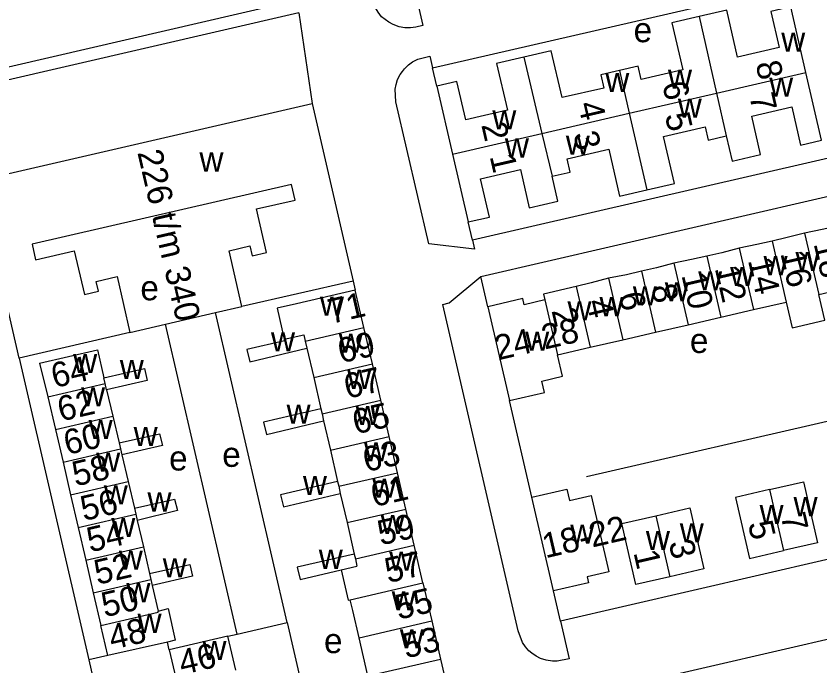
# Model space of a CAD drawing. Extents: x 155696 to 157795, y 382328 to 384028.
# Drawn here: x 156988.1 to 157117.5, y 383345.7 to 383450.5 of the extents above; entities that cross this region are included whole.
import ezdxf

# ---------------------------------------------------------------- set-up
doc = ezdxf.new("R2010")
doc.units = 0
for name, color, linetype in [('BLT_Basislijn', 7, 'Continuous'), ('BLT_Bebouwing', 7, 'Continuous'), ('BLT_Centroide', 7, 'Continuous'), ('BLT_Huisnummer', 7, 'Continuous'), ('BLT_Huisnummer_ tussenligend', 7, 'Continuous'), ('BLT_Huisnummer_reeks', 7, 'Continuous'), ('BLT_Onderverdeling_panden', 7, 'Continuous'), ('BLT_Vlakafsluiter', 7, 'Continuous')]:
    doc.layers.add(name, color=color, linetype=linetype)

msp = doc.modelspace()

# ---------------------------------------------------------------- linework, layer by layer
at = {"layer": 'BLT_Basislijn'}
for p, q in [((157055.84, 383439.14), (157055.17, 383442.1)), ((157061.59, 383414.33), (157060.9, 383417.29)), ((157042.38, 383407.74), (157042.71, 383406.28)), ((157020.2, 383402.66), (157024.45, 383403.65)), ((157012.15, 383400.78), (157020.2, 383402.66)), ((157031.74, 383352.71), (157020.2, 383402.66)), ((157006.4, 383399.44), (157012.15, 383400.78)), ((157023.69, 383350.85), (157012.15, 383400.78)), ((156988.59, 383395.32), (156999.79, 383346.69)), ((157079.95, 383376.24), (157134.89, 383388.93)), ((157023.69, 383350.85), (157031.74, 383352.71)), ((157031.74, 383352.71), (157043.15, 383303.31)), ((157022.19, 383350.5), (157023.69, 383350.85)), ((157012.74, 383348.32), (157012.45, 383349.58)), ((157002.84, 383347.39), (156999.79, 383346.69)), ((156999.79, 383346.69), (157000.9, 383341.9))]:
    msp.add_line(p, q, dxfattribs=at)
for points in [[(157052.14, 383455.26), (157053.59, 383448.93), (157052.46, 383448.65), (157051.62, 383448.56), (157050.71, 383448.57), (157049.79, 383448.74), (157048.82, 383449.07), (157048.11, 383449.45), (157046.95, 383450.35), (157046.39, 383451.07), (157045.95, 383451.78), (157045.59, 383452.7), (157045.31, 383453.68), (157039.57, 383478.52), (157040.6, 383478.76), (157045.72, 383483.02)], [(157055.17, 383442.1), (157119.26, 383456.9)], [(157119.26, 383456.9), (157125.67, 383429.13), (157061.59, 383414.33)], [(157033.62, 383450.98), (156911.34, 383422.73)], [(157061.59, 383414.33), (157061.92, 383412.88), (157054.54, 383413.74), (157049.25, 383436.64), (157049.13, 383438.66), (157049.3, 383439.42), (157049.52, 383440.21), (157049.94, 383441.03), (157050.31, 383441.54), (157050.62, 383441.97), (157051.28, 383442.61), (157051.93, 383443.08), (157052.79, 383443.52), (157054.74, 383443.98), (157055.17, 383442.1)], [(157062.94, 383408.49), (157127.02, 383423.29), (157135.23, 383387.74)], [(157075.77, 383352.95), (157077.17, 383346.85), (157075.2, 383346.51), (157074.45, 383346.49), (157073.46, 383346.64), (157072.54, 383346.93), (157071.86, 383347.28), (157071.14, 383347.8), (157070.68, 383348.17), (157070.12, 383348.8), (157069.65, 383349.49), (157068.94, 383351.38), (157056.79, 383403.99), (157057.81, 383404.23), (157062.94, 383408.49)], [(157064.06, 383403.61), (157062.94, 383408.49)], [(157071.15, 383372.94), (157067.56, 383388.49)], [(157139.85, 383367.75), (157075.77, 383352.95)], [(157075.77, 383352.95), (157074.64, 383357.82)], [(157078.58, 383340.77), (157142.66, 383355.57), (157152.05, 383314.94)]]:
    msp.add_lwpolyline(points, dxfattribs=at)
at = {"layer": 'BLT_Bebouwing'}
for p, q in [((157115.3, 383441.36), (157112.86, 383451.95)), ((157055.84, 383439.14), (157058.38, 383428.22)), ((157042.38, 383407.74), (157024.45, 383403.65)), ((157042.71, 383406.28), (157033.26, 383404.1)), ((157044.11, 383400.24), (157042.71, 383406.28)), ((157117.38, 383405.58), (157122.64, 383406.8)), ((157106.85, 383403.15), (157112.12, 383404.37)), ((157030.12, 383403.37), (157031.27, 383398.36)), ((157101.59, 383401.94), (157106.85, 383403.15)), ((157096.33, 383400.72), (157101.59, 383401.94)), ((157091.07, 383399.51), (157096.33, 383400.72)), ((157006.4, 383399.44), (156988.59, 383395.32)), ((157045.46, 383394.4), (157044.11, 383400.24)), ((157085.81, 383398.29), (157091.07, 383399.51)), ((157080.55, 383397.08), (157085.81, 383398.29)), ((156991.85, 383394.54), (157001.19, 383396.67)), ((157001.19, 383396.67), (157002.2, 383392.17)), ((157034.91, 383396.91), (157036.01, 383392.21)), ((157075.29, 383395.86), (157080.55, 383397.08)), ((156991.85, 383394.54), (156993.21, 383389.1)), ((157046.81, 383388.55), (157045.46, 383394.4)), ((157036.01, 383392.21), (157037.16, 383387.14)), ((157002.65, 383390.24), (157003.66, 383385.97)), ((156993.21, 383389.1), (156994.43, 383383.84)), ((157048.16, 383382.71), (157046.81, 383388.55)), ((157003.66, 383385.97), (157004.67, 383381.66)), ((157037.61, 383385.2), (157038.71, 383380.52)), ((156994.43, 383383.84), (156995.64, 383378.57)), ((157049.51, 383376.86), (157048.16, 383382.71)), ((157005.11, 383379.76), (157006.12, 383375.45)), ((157038.71, 383380.52), (157039.85, 383375.45)), ((156995.64, 383378.57), (156996.86, 383373.31)), ((157050.86, 383371.01), (157049.51, 383376.86)), ((157006.12, 383375.45), (157007.13, 383371.15)), ((156996.86, 383373.31), (156998.07, 383368.05)), ((157040.29, 383373.52), (157041.41, 383368.83)), ((157052.21, 383365.17), (157050.86, 383371.01)), ((157007.6, 383369.18), (157008.57, 383364.93)), ((157041.41, 383368.83), (157042.54, 383363.76)), ((156998.07, 383368.05), (156999.29, 383362.79)), ((157008.57, 383364.93), (157009.56, 383360.62)), ((157053.61, 383359.12), (157052.21, 383365.17)), ((156999.29, 383362.79), (157000.5, 383357.53)), ((157053.61, 383359.12), (157055.02, 383352.98)), ((157010.01, 383358.67), (157010.94, 383354.57)), ((157000.5, 383357.53), (157001.72, 383352.26)), ((157042.32, 383354.66), (157041.9, 383356.39)), ((157043.33, 383350.28), (157042.32, 383354.66)), ((157055.02, 383352.98), (157056.44, 383346.84)), ((157002.84, 383347.39), (157001.72, 383352.26)), ((157022.19, 383350.5), (157012.74, 383348.32)), ((157023.45, 383345.04), (157022.19, 383350.5)), ((157044.75, 383344.14), (157043.33, 383350.28)), ((157012.45, 383349.58), (157002.84, 383347.39)), ((157013.71, 383349.87), (157012.45, 383349.58)), ((157012.74, 383348.32), (157014, 383342.86)), ((157056.44, 383346.84), (157057.86, 383340.7))]:
    msp.add_line(p, q, dxfattribs=at)
msp.add_lwpolyline([(156963.49, 383462.53), (157024.61, 383476.65), (157030.25, 383452.25), (156920.89, 383426.99), (156941.26, 383444.13), (156972.68, 383451.38)], close=True, dxfattribs=at)
for points in [[(157112.86, 383451.95), (157109.63, 383451.2), (157110.97, 383445.38), (157104.28, 383443.83), (157102.54, 383451.39), (157098.12, 383450.37)], [(157098.12, 383450.37), (157093.71, 383449.35), (157095.46, 383441.79), (157088.75, 383440.24), (157088.25, 383442.39), (157085.25, 383441.69)], [(157085.25, 383441.69), (157082.24, 383441), (157082.74, 383438.86), (157076.03, 383437.31), (157074.28, 383444.87), (157069.87, 383443.85)], [(157069.87, 383443.85), (157065.45, 383442.83), (157067.2, 383435.27), (157060.49, 383433.72), (157059.08, 383439.89), (157055.84, 383439.14)], [(157102.47, 383431.13), (157103.4, 383427.09), (157107.98, 383428.15), (157106.56, 383434.33), (157113, 383435.82), (157114.42, 383429.66), (157117.82, 383430.44), (157115.3, 383441.36)], [(156988.59, 383395.32), (156981.98, 383423.96), (157035.76, 383436.39)], [(157035.76, 383436.39), (157042.38, 383407.74)], [(157089.69, 383422.47), (157094.1, 383423.49), (157092.35, 383431.05), (157099.06, 383432.6), (157099.56, 383430.46), (157102.47, 383431.13)], [(157074.4, 383424.65), (157077.31, 383425.32), (157076.82, 383427.46), (157083.53, 383429.01), (157085.27, 383421.45), (157089.69, 383422.47)], [(157058.38, 383428.22), (157060.9, 383417.29)], [(157060.9, 383417.29), (157064.31, 383418.07), (157062.88, 383424.24), (157069.31, 383425.73), (157070.74, 383419.54), (157075.34, 383420.6), (157074.4, 383424.65)], [(157024.45, 383403.65), (157022.38, 383412.64), (157025.73, 383413.41), (157026.1, 383411.81), (157028.39, 383412.34), (157026.77, 383419.37), (157033.02, 383420.81), (157032.45, 383423.32), (156990.64, 383413.67), (156991.2, 383411.19), (156997.45, 383412.62), (156999.07, 383405.58), (157001.34, 383406.1), (157000.98, 383407.69), (157004.33, 383408.46), (157006.4, 383399.44)], [(157120.37, 383416.62), (157117.93, 383416.06), (157115.08, 383415.49)], [(157115.08, 383415.49), (157112.28, 383414.75), (157109.85, 383414.19)], [(157109.85, 383414.19), (157107.41, 383413.63), (157104.55, 383413.06)], [(157104.55, 383413.06), (157101.76, 383412.32), (157099.32, 383411.76)], [(157099.32, 383411.76), (157096.89, 383411.2), (157094.03, 383410.63)], [(157094.03, 383410.63), (157091.24, 383409.89), (157088.8, 383409.33)], [(157088.8, 383409.33), (157086.37, 383408.77), (157083.5, 383408.19)], [(157083.5, 383408.19), (157080.71, 383407.46), (157078.28, 383406.9)], [(157078.28, 383406.9), (157073.02, 383405.64), (157073.24, 383404.71)], [(157073.24, 383404.71), (157069.92, 383403.94), (157069.69, 383404.92), (157064.06, 383403.61)], [(157112.12, 383404.37), (157113.06, 383400.23), (157118.33, 383401.44), (157117.38, 383405.58)], [(157033.26, 383404.1), (157030.12, 383403.37)], [(157064.06, 383403.61), (157067.56, 383388.49)], [(157031.27, 383398.36), (157031.33, 383398.12), (157025.25, 383396.7), (157025.7, 383394.76), (157034.91, 383396.91)], [(157067.56, 383388.49), (157073.19, 383389.79), (157072.76, 383391.64), (157076.08, 383392.41), (157075.29, 383395.86)], [(157002.2, 383392.17), (157008.73, 383393.65), (157009.19, 383391.73), (157002.65, 383390.24)], [(157037.16, 383387.14), (157027.95, 383385), (157028.41, 383383.05), (157037.61, 383385.2)], [(157004.67, 383381.66), (157011.17, 383383.14), (157011.63, 383381.24), (157005.11, 383379.76)], [(157039.85, 383375.45), (157030.66, 383373.31), (157031.12, 383371.38), (157040.29, 383373.52)], [(157109.43, 383374.15), (157114.9, 383375.41), (157117.17, 383365.59), (157111.7, 383364.33)], [(157071.15, 383372.94), (157076.78, 383374.24), (157077.21, 383372.39), (157080.71, 383373.2), (157080.71, 383373.2)], [(157109.43, 383374.15), (157103.97, 383372.89), (157106.23, 383363.06), (157111.7, 383364.33)], [(157007.13, 383371.15), (157013.6, 383372.62), (157014.05, 383370.76), (157007.6, 383369.18)], [(157074.64, 383357.82), (157071.15, 383372.94)], [(157080.71, 383373.2), (157083.55, 383360.91)], [(157091.12, 383369.92), (157096.58, 383371.18), (157098.85, 383361.36), (157093.39, 383360.1)], [(157093.39, 383360.1), (157087.92, 383358.83), (157085.65, 383368.66), (157091.12, 383369.92)], [(157042.54, 383363.76), (157033.36, 383361.62), (157033.81, 383359.68), (157040.46, 383361.22)], [(157009.56, 383360.62), (157016.06, 383362.1), (157016.49, 383360.17), (157010.01, 383358.67)], [(157040.46, 383361.22), (157041.56, 383356.32), (157041.9, 383356.39)], [(157083.55, 383360.91), (157080.05, 383360.09), (157080.27, 383359.12), (157074.64, 383357.82)], [(157010.94, 383354.57), (157012.55, 383354.96), (157013.71, 383349.87)]]:
    msp.add_lwpolyline(points, dxfattribs=at)
at = {"layer": 'BLT_Onderverdeling_panden'}
for p, q in [((157098.12, 383450.37), (157100.91, 383438.04)), ((157069.87, 383443.85), (157072.78, 383431.54)), ((157085.25, 383441.69), (157086.84, 383434.79)), ((157100.91, 383438.04), (157115.3, 383441.36)), ((157086.84, 383434.79), (157100.91, 383438.04)), ((157100.91, 383438.04), (157102.47, 383431.13)), ((157072.78, 383431.54), (157086.84, 383434.79)), ((157086.84, 383434.79), (157089.69, 383422.47)), ((157058.38, 383428.22), (157072.78, 383431.54)), ((157072.78, 383431.54), (157074.4, 383424.65)), ((157115.08, 383415.49), (157117.38, 383405.58)), ((157109.85, 383414.19), (157112.12, 383404.37)), ((157104.55, 383413.06), (157106.85, 383403.15)), ((157099.32, 383411.76), (157101.59, 383401.94)), ((157094.03, 383410.63), (157096.33, 383400.72)), ((157088.8, 383409.33), (157091.07, 383399.51)), ((157083.5, 383408.19), (157085.81, 383398.29)), ((157078.28, 383406.9), (157080.55, 383397.08)), ((157073.24, 383404.71), (157075.29, 383395.86)), ((157034.66, 383398.06), (157044.11, 383400.24)), ((157034.42, 383399.08), (157034.66, 383398.06)), ((157034.66, 383398.06), (157034.91, 383396.91)), ((157036.01, 383392.21), (157045.46, 383394.4)), ((157002.42, 383391.22), (157002.2, 383392.17)), ((156993.21, 383389.1), (157002.42, 383391.22)), ((157002.65, 383390.24), (157002.42, 383391.22)), ((157037.36, 383386.37), (157046.81, 383388.55)), ((157037.16, 383387.14), (157037.36, 383386.37)), ((157037.36, 383386.37), (157037.61, 383385.2)), ((156994.43, 383383.84), (157003.66, 383385.97)), ((157038.71, 383380.52), (157048.16, 383382.71)), ((157004.67, 383381.66), (157004.89, 383380.71)), ((156995.64, 383378.57), (157004.89, 383380.71)), ((157004.89, 383380.71), (157005.11, 383379.76)), ((157040.06, 383374.68), (157049.51, 383376.86)), ((156996.86, 383373.31), (157006.12, 383375.45)), ((157039.85, 383375.45), (157040.06, 383374.68)), ((157040.06, 383374.68), (157040.29, 383373.52)), ((157109.43, 383374.15), (157111.7, 383364.33)), ((157007.13, 383371.15), (157007.36, 383370.2)), ((157041.41, 383368.83), (157050.86, 383371.01)), ((156998.07, 383368.05), (157007.36, 383370.2)), ((157007.36, 383370.2), (157007.6, 383369.18)), ((157091.12, 383369.92), (157093.39, 383360.1)), ((156999.29, 383362.79), (157008.57, 383364.93)), ((157042.76, 383362.98), (157052.21, 383365.17)), ((157042.54, 383363.76), (157042.76, 383362.98)), ((157042.76, 383362.98), (157042.98, 383361.81)), ((157040.46, 383361.22), (157042.98, 383361.81)), ((157009.56, 383360.62), (157009.79, 383359.67)), ((157000.5, 383357.53), (157009.79, 383359.67)), ((157009.79, 383359.67), (157010.01, 383358.67)), ((157041.9, 383356.39), (157053.61, 383359.12)), ((157001.72, 383352.26), (157010.98, 383354.4)), ((157010.98, 383354.4), (157010.94, 383354.57)), ((157043.33, 383350.28), (157055.02, 383352.98)), ((157044.75, 383344.14), (157056.44, 383346.84))]:
    msp.add_line(p, q, dxfattribs=at)
msp.add_lwpolyline([(157031.27, 383398.36), (157034.42, 383399.08)], dxfattribs=at)
at = {"layer": 'BLT_Vlakafsluiter'}
msp.add_line((157033.62, 383450.98), (157035.76, 383436.39), dxfattribs=at)

# ---------------------------------------------------------------- texts
at = {"layer": 'BLT_Centroide'}
for s, p in [('e', (157087.54, 383446.24)), ('w', (157111.32, 383444.72)), ('w', (157082.98, 383438.22)), ('w', (157093.08, 383438.73)), ('w', (157109.38, 383437.48)), ('w', (157094.66, 383434.09)), ('w', (157064.78, 383432.2)), ('w', (157066.81, 383427.66)), ('w', (157076.62, 383428.12)), ('w', (157017.61, 383425.4)), ('w', (157113.61, 383409.38)), ('w', (157108.47, 383408.7)), ('w', (157103.09, 383406.94)), ('w', (157097.94, 383406.27)), ('e', (157008.09, 383404.65)), ('w', (157092.56, 383404.5)), ('w', (157087.42, 383403.83)), ('w', (157037.02, 383402.16)), ('w', (157076.89, 383401.41)), ('w', (157082.05, 383402.09)), ('w', (157029.13, 383396.4)), ('w', (157040.05, 383396.22)), ('w', (157070.08, 383396.52)), ('e', (157096.61, 383396.16)), ('w', (156997.27, 383392.91)), ('w', (157004.78, 383391.96)), ('w', (157041.41, 383390.38)), ('w', (156998.54, 383387.56)), ('w', (157031.64, 383384.77)), ('w', (157042.76, 383384.53)), ('w', (156999.76, 383382.28)), ('w', (157007.01, 383381.16)), ('w', (157044.11, 383378.69)), ('w', (157000.98, 383377.03)), ('e', (157012.72, 383377.22)), ('e', (157021.28, 383377.81)), ('w', (157034.28, 383373.28)), ('w', (157045.46, 383372.84)), ('w', (157002.2, 383371.78)), ('w', (157009.24, 383370.61)), ('w', (157113.3, 383369.86)), ('w', (157107.83, 383368.61)), ('w', (157003.41, 383366.5)), ('w', (157046.8, 383367)), ('w', (157077.34, 383365.44)), ('w', (157094.98, 383365.64)), ('w', (157089.52, 383364.39)), ('w', (157004.62, 383361.25)), ('w', (157036.83, 383361.37)), ('w', (157011.7, 383359.99)), ('w', (157048.18, 383361.06)), ('w', (157005.84, 383356)), ('w', (157048.57, 383354.69)), ('w', (157007.64, 383351.06)), ('w', (157049.89, 383348.56)), ('e', (157037.67, 383347.79)), ('w', (157018.1, 383346.69))]:
    msp.add_text(s, height=4, dxfattribs=at).set_placement(p)
at = {"layer": 'BLT_Huisnummer'}
for s, rotation, p in [('8', 283.006, (157107.16, 383442.8)), ('7', 283.0058, (157106.14, 383437.6)), ('5', 283.0058, (157092.55, 383434.49)), ('2', 283.006, (157062.99, 383432.92)), ('1', 283.0058, (157064.34, 383427.85)), ('16', 283.0062, (157111.16, 383412.23)), ('12', 283.0062, (157100.59, 383409.82)), ('71', 13.014, (157038.82, 383400.83)), ('6', 283.0062, (157085.11, 383405.57)), ('2', 283.0062, (157074.3, 383403)), ('64', 13.0119, (156994.24, 383390.49)), ('67', 13.014, (157041.4, 383388.75)), ('65', 13.014, (157042.76, 383383.02)), ('60', 13.0119, (156996.26, 383379.7)), ('61', 13.014, (157045.72, 383371.31)), ('56', 13.0119, (156998.96, 383369.07)), ('7', 283.0063, (157111.2, 383369.95)), ('57', 13.014, (157047.97, 383359.06)), ('1', 283.0063, (157087.5, 383364)), ('52', 13.0119, (157001.16, 383358.78)), ('48', 13.0119, (157003.51, 383348.32)), ('53', 13.014, (157050.85, 383346.92)), ('46', 13.0119, (157014.8, 383344.27))]:
    msp.add_text(s, height=4, rotation=rotation, dxfattribs=at).set_placement(p)
at = {"layer": 'BLT_Huisnummer_ tussenligend'}
for s, rotation, p in [('6', 283.006, (157092.12, 383439.51)), ('4', 283.006, (157078.56, 383436.28)), ('3', 283.0058, (157077.79, 383431.46)), ('18', 283.0062, (157116.52, 383413.78)), ('14', 283.0062, (157105.94, 383411.1)), ('10', 283.0062, (157095.23, 383408.7)), ('8', 283.0062, (157090.33, 383406.83)), ('4', 283.0062, (157079.9, 383404.44)), ('69', 13.014, (157040.39, 383394.48)), ('62', 13.0119, (156995.26, 383385.1)), ('63', 13.014, (157044.44, 383376.94)), ('58', 13.0119, (156997.62, 383374.64)), ('59', 13.014, (157046.8, 383365.13)), ('54', 13.0119, (156999.97, 383364.01)), ('5', 283.0063, (157105.93, 383368.68)), ('3', 283.0063, (157093.17, 383365.59)), ('50', 13.0119, (157002.33, 383353.55)), ('55', 13.014, (157049.67, 383353.16))]:
    msp.add_text(s, height=4, rotation=rotation, dxfattribs=at).set_placement(p)
at = {"layer": 'BLT_Huisnummer_reeks'}
for s, rotation, p in [('226 t/m 340', 283.0068, (157007.59, 383428.49)), ('24-28', 13.0062, (157065.68, 383394.96)), ('18-22', 13.0062, (157073.34, 383363.06))]:
    msp.add_text(s, height=4, rotation=rotation, dxfattribs=at).set_placement(p)

doc.saveas('drawing.dxf')
